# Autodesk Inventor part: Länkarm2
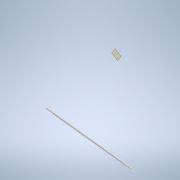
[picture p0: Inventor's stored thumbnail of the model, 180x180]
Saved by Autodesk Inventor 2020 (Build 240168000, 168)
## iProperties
Created: 2019-07
Part Number: Länkarm2
Material: Generic
Document SubType Name: Modeling
Designer: cl
Density: 1 g/cm^3
Appearance: Default
Author: cl
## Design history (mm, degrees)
workplane "Work Plane1"
sketch "Sketch1"
  geometry: L1 (1048.998, -1301.615)-(-355.7, -1956.58); L2 (1048.998, -1301.615)-(-355.7, -1956.58); L3 (-337.574, -1948.129)-(-341.8, -1939.065); L4 (-341.8, -1939.065)-(-260.231, -1901.032); L5 (-260.231, -1901.032)-(-262.344, -1896.501); L6 (-262.344, -1896.501)-(961.09, -1326.053); L7 (961.09, -1326.053)-(963.203, -1330.585); L8 (963.203, -1330.585)-(1044.772, -1292.552); L9 (1044.772, -1292.552)-(1048.998, -1301.615); L10 (-337.574, -1948.129)-(1048.998, -1301.615); L11 (1048.998, -1301.615)-(1113.278, -1271.644); C1 r 6 at (1067.125, -1293.163) reference; C2 r 6 at (-355.7, -1956.58) reference; 4 further points
  constraints: 23 end point, 6 perpendicular, 2 point on line, 1 coincident, 1 collinear
  dimensions: "d0" = 10 distance of L3.start L3.end; "d1" = 90 distance of L3.end L4.end; "d2" = 5 distance of L4.end L5.end; "d3" = 5 distance of L6.end L7.end; "d5" = 90 distance of L7.end L8.end; "d7" = 10 distance of L1.start L8.end; "d37" = 20 distance from line of C1.centre L9; "d39" = 20 distance from line of L1.end L3
revolve "Revolution1" sketch "Sketch1" stored, may be unused: angle "d9" = 90 deg
fillet "Fillet1" dims "d10" = 5
sketch "Sketch2"
  geometry: L1 (-340.743, -1941.331)-(-358.87, -1949.783); L2 (-358.87, -1949.783)-(-352.531, -1963.378); L3 (-352.531, -1963.378)-(-334.404, -1954.926); L4 (-334.404, -1954.926)-(-340.743, -1941.331); L5 (-333.348, -1957.192)-(-341.8, -1939.065) reference; L6 (1045.829, -1294.818)-(1063.955, -1286.366); L7 (1063.955, -1286.366)-(1070.294, -1299.961); L8 (1070.294, -1299.961)-(1052.168, -1308.413); L9 (1052.168, -1308.413)-(1045.829, -1294.818); L10 (1053.224, -1310.678)-(1044.772, -1292.552) reference; 1 further point
  constraints: 16 end point, 6 perpendicular, 2 collinear
  dimensions: "d11" = 20 distance of L3.end L2.end; "d12" = 15 distance of L2.end L1.end; "d13" = 2.5 distance from line of L5.end L1; "d22" = 20 distance of L7.end L8.end; "d23" = 15 distance of L6.end L7.end; "d24" = 2.5 distance from line of L6 L10.end
extrude "Extrusion1" join sketch "Sketch2" stored distance "d14" = 4; taper "d15" = 0 deg
sketch "Sketch3"
  geometry: L1 (-358.87, -1949.783)-(-352.531, -1963.378) reference; C1 r 10 at (-355.7, -1956.58); 1 further point
  constraints: 1 centre point, 1 midpoint
  dimensions: "d16" = 20 diameter of C1
extrude "Extrusion2" join sketch "Sketch3" distance "d17" = 8; taper "d19" = 0 deg; dims "d18" = 48, "d20" = 0
sketch "Sketch4"
  geometry: L1 (-1070.294, -1299.961)-(-1063.955, -1286.366) reference; C1 r 10 at (-1067.125, -1293.163); 1 further point
  constraints: 1 centre point, 1 midpoint
  dimensions: "d29" = 20 diameter of C1
extrude "Extrusion3" join sketch "Sketch4" distance "d30" = 4; taper "d32" = 0 deg; dims "d31" = 52, "d33" = 0
fillet "Fillet3" dims "d34" = 5
body "Solid1"
node "Projected Loop1"
node "Reference7"
node "Reference8"
